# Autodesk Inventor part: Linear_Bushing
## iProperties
Author: cdotson
Shininess: 50.0
PropertySet Name: _Private Model Information
Created: 2001-02
Part Number: Linear_Bushing
Material: Aluminum-6061
Document SubType Name: Modeling
Designer: cdotson
Control State: 0
Master: False
Checked Out: False
PropertySet Name: Design Tracking Control
Density: 2.71
Volumn: 1.776797940228691
Area: 13.728802679842369
PropertySet Name: Model Information
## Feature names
1. Extrusion2
2. Revolution1
3. Fillet1
4. Extrusion3
5. Extrusion4
